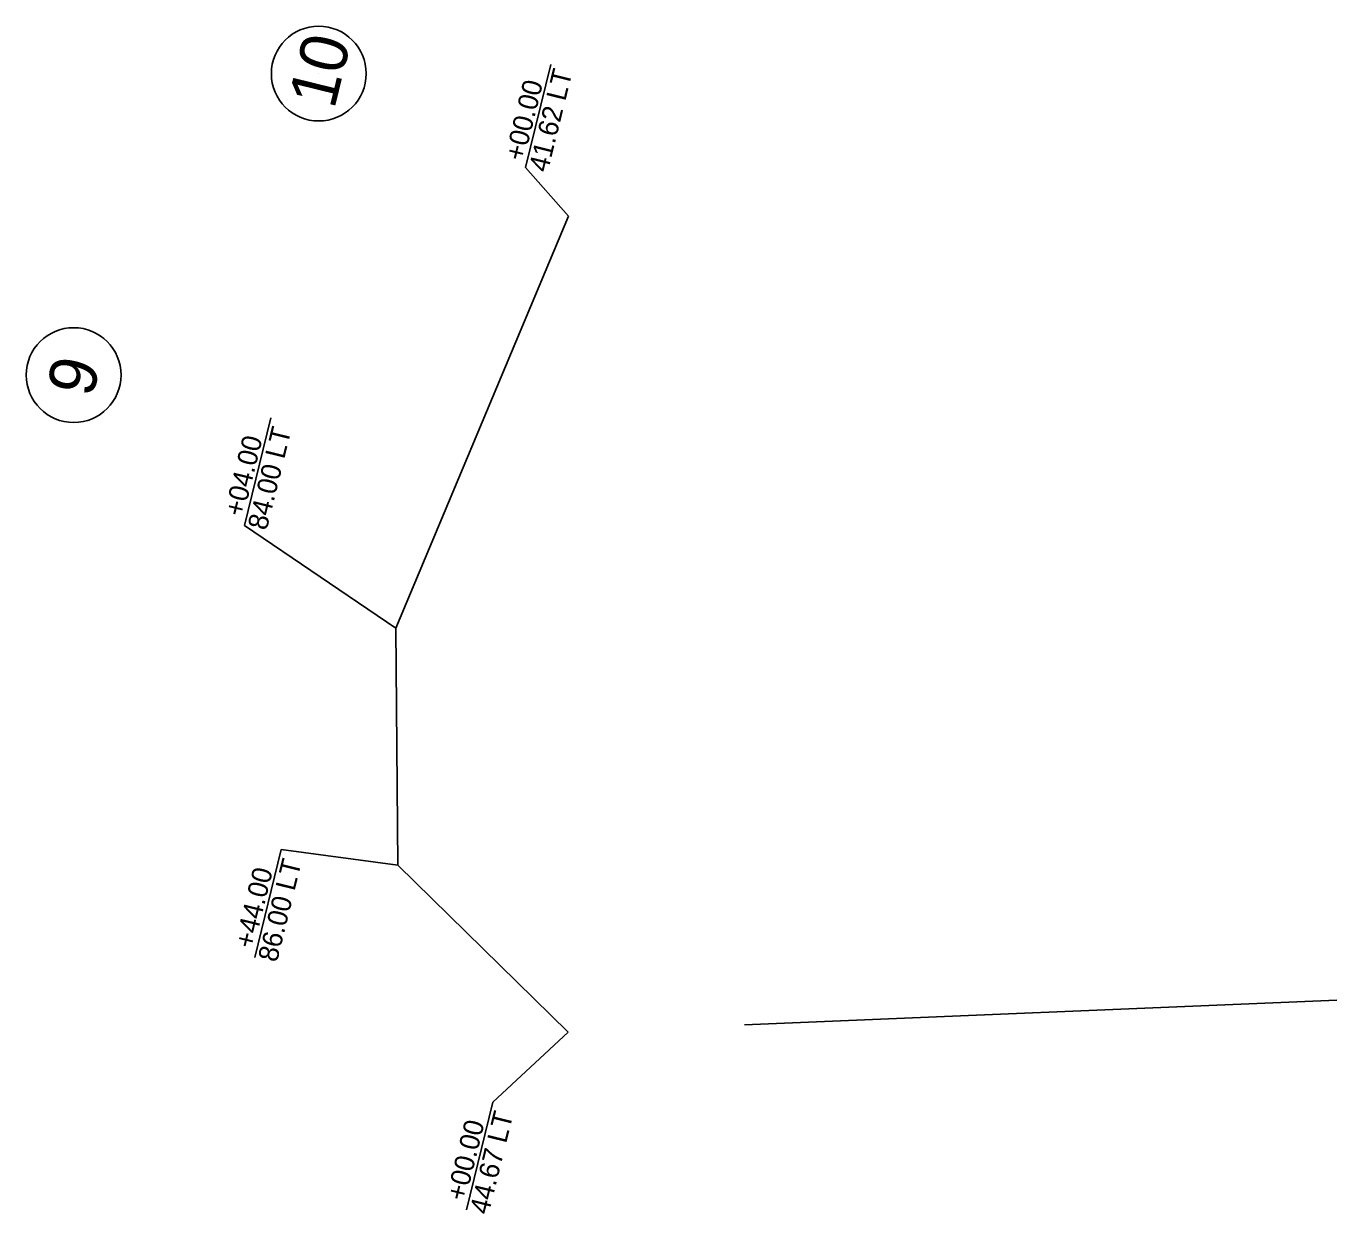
# Model space of a CAD drawing. Extents: x 1002576 to 1014655, y 551673 to 557994.
# Drawn here: x 1004837.4 to 1005169, y 553929.3 to 554230 of the extents above; entities that cross this region are included whole.
import ezdxf

# ---------------------------------------------------------------- set-up
doc = ezdxf.new("R2010")
doc.units = 0
for name, color, linetype in [('Exist DTM Crownline', 7, 'Continuous'), ('Exist Guardrail', 7, 'Continuous'), ('Exist Roads Soil Text', 7, 'Continuous'), ('Exist Utilities Power Pole CELL', 7, 'Continuous')]:
    doc.layers.add(name, color=color, linetype=linetype)

msp = doc.modelspace()

# ---------------------------------------------------------------- linework, layer by layer
at = {"layer": 'Exist DTM Crownline'}
for p, q in [((1004931.38, 554017.57), (1004930.88, 554077.6)), ((1005019.15, 553977.19), (1005169.01, 553983.45))]:
    msp.add_line(p, q, dxfattribs=at)
at = {"layer": 'Exist Guardrail'}
for p, q in [((1004930.88, 554077.6), (1004974.61, 554181.88)), ((1004931.38, 554017.57), (1004930.88, 554077.6)), ((1004974.51, 553975.33), (1004931.38, 554017.57))]:
    msp.add_line(p, q, dxfattribs=at)
at = {"layer": 'Exist Roads Soil Text'}
for p, q in [((1004970.13, 554220.34), (1004963.7, 554194.2)), ((1004899.3, 554130.87), (1004892.58, 554103.57)), ((1004901.9, 554021.52), (1004895.18, 553994.21)), ((1004955.47, 553957.61), (1004948.75, 553930.3))]:
    msp.add_line(p, q, dxfattribs=at)
for points in [[(1004963.7, 554194.2), (1004974.61, 554181.88)], [(1004892.58, 554103.57), (1004930.88, 554077.6)], [(1004901.9, 554021.52), (1004931.38, 554017.57)], [(1004955.47, 553957.61), (1004974.51, 553975.33)]]:
    msp.add_lwpolyline(points, dxfattribs=at)
at = {"layer": 'Exist Utilities Power Pole CELL'}
for p, q in [((1004911.39, 554218.01), (1004911.39, 554218.01)), ((1004849.36, 554141.68), (1004849.36, 554141.68))]:
    msp.add_line(p, q, dxfattribs=at)
for centre in [(1004911.39, 554218.01), (1004849.36, 554141.68)]:
    msp.add_circle(centre, 12, dxfattribs=at)

# ---------------------------------------------------------------- texts
at = {"layer": 'Exist Roads Soil Text'}
for s, p in [('41.62 LT', (1004969.31, 554192.8)), ('+00.00', (1004963.25, 554195.63)), ('84.00 LT', (1004898.18, 554102.17)), ('+04.00', (1004892.27, 554105.59)), ('86.00 LT', (1004900.79, 553992.81)), ('+44.00', (1004894.88, 553996.23)), ('+00.00', (1004948.45, 553932.32)), ('44.67 LT', (1004954.35, 553928.9))]:
    msp.add_text(s, height=5, rotation=76.1775, dxfattribs=at).set_placement(p)
at = {"layer": 'Exist Utilities Power Pole CELL'}
for s, p in [('10', (1004915.29, 554208.76)), ('9', (1004854.07, 554135.74))]:
    msp.add_text(s, height=12, rotation=76.1775, dxfattribs=at).set_placement(p)

doc.saveas('drawing.dxf')
